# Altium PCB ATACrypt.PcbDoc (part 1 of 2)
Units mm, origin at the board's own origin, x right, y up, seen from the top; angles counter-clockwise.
Board outline 105.66 x 138.68 mm, 2 copper layers (Top Layer, Bottom Layer); 134 components, 213 nets, 662 pads, 171 vias.
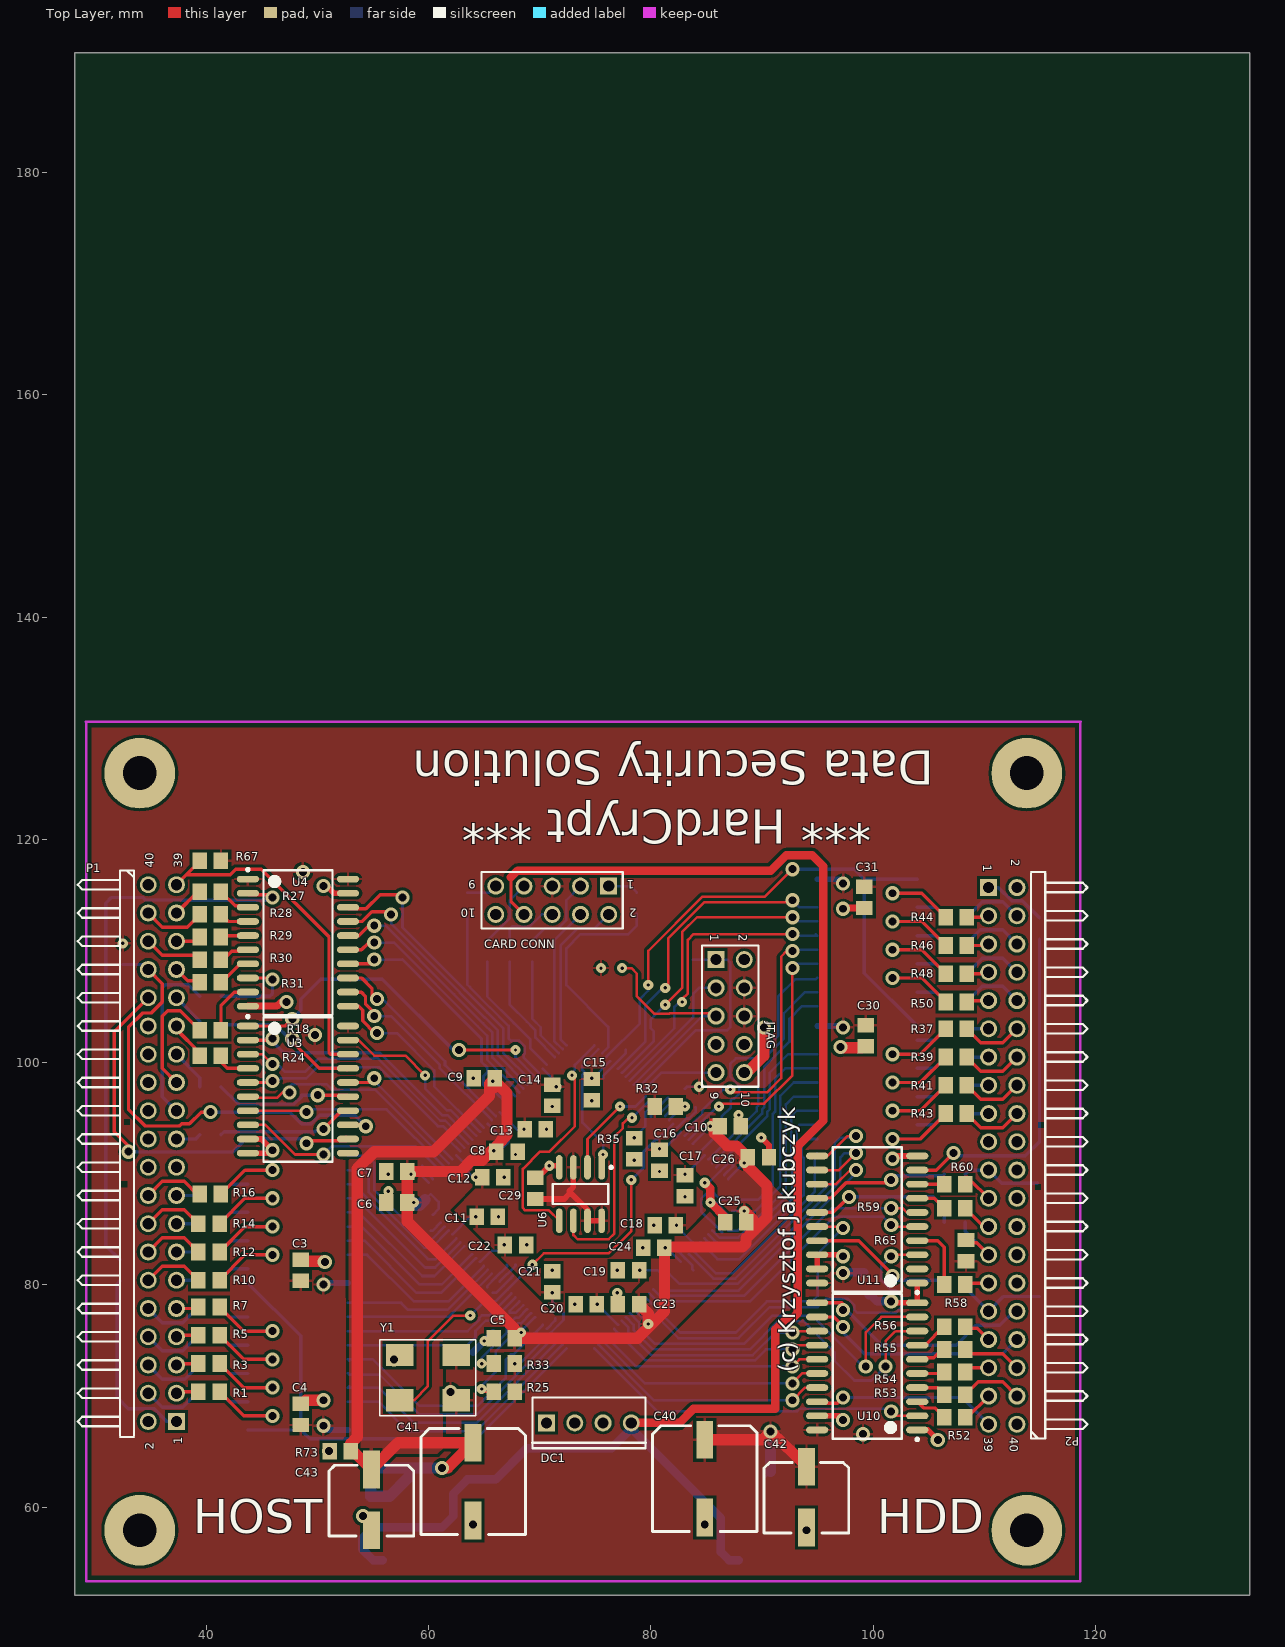
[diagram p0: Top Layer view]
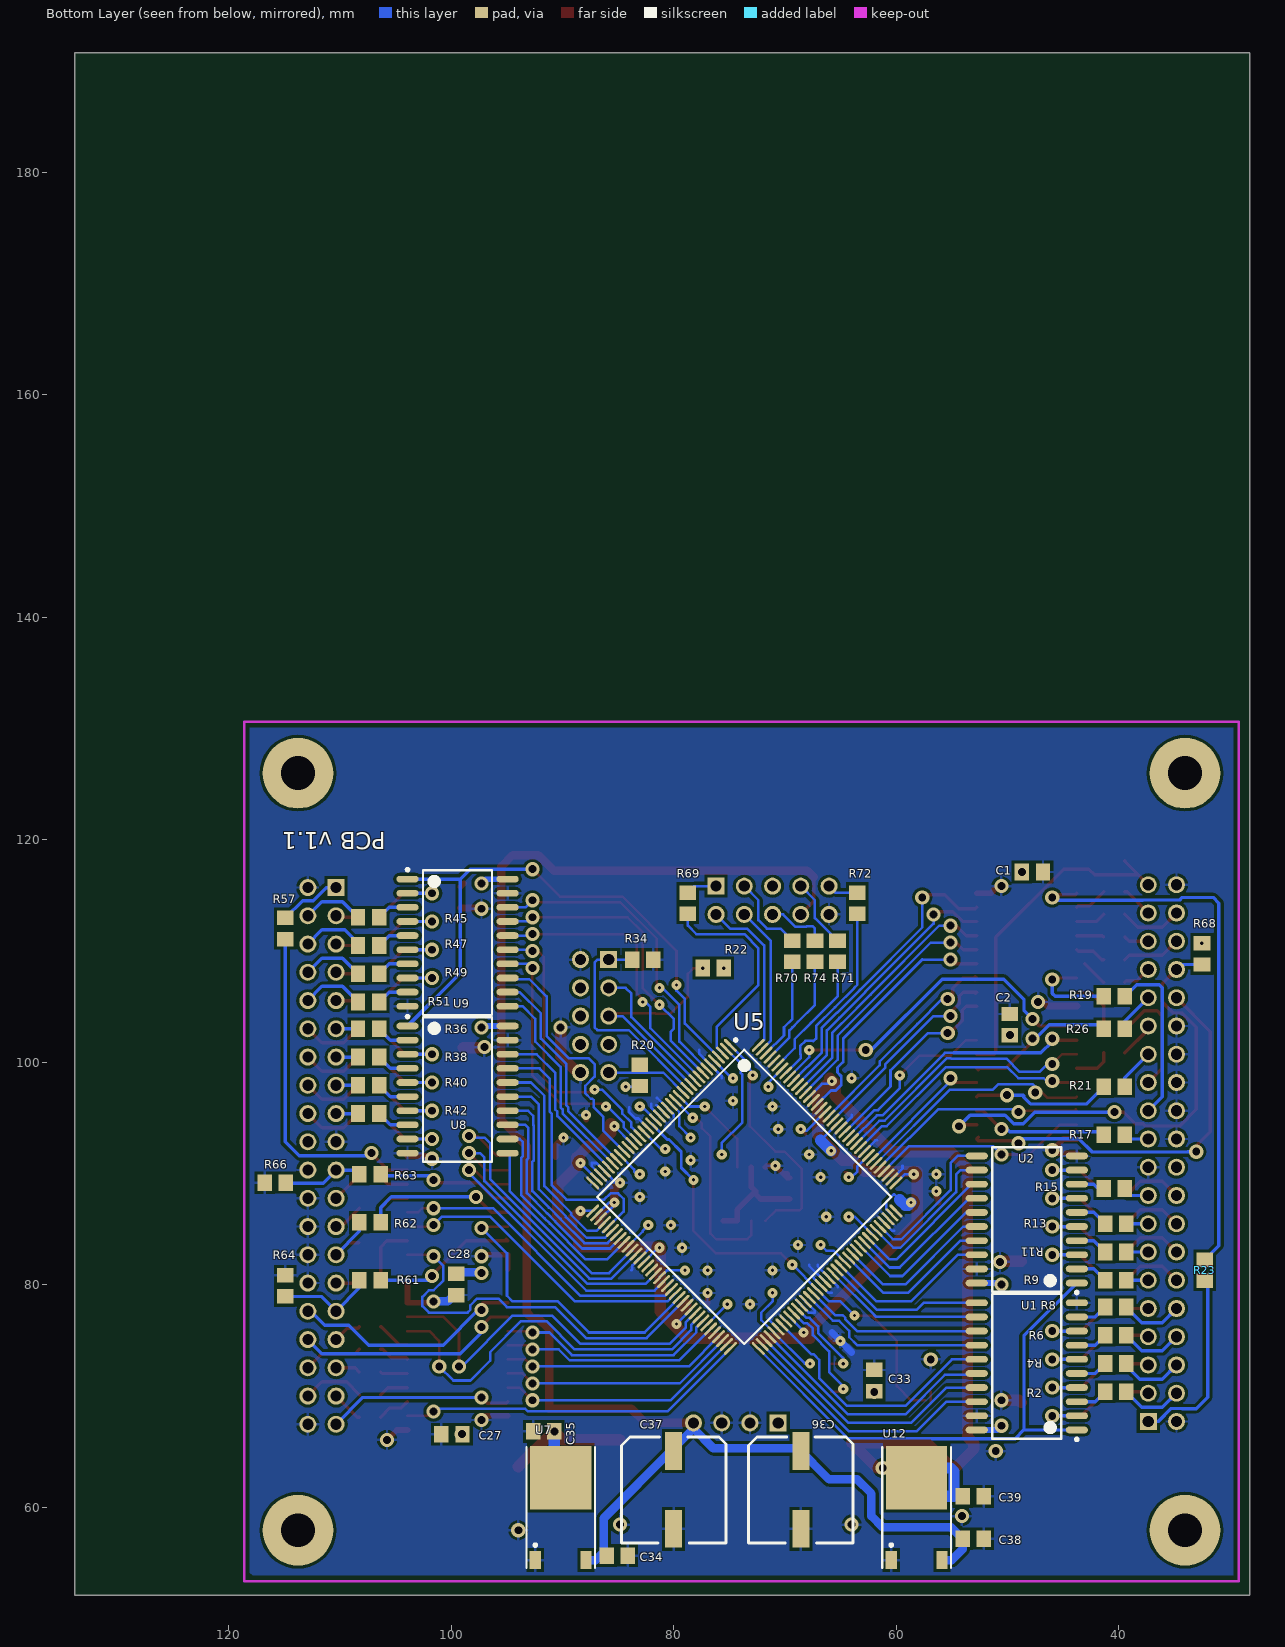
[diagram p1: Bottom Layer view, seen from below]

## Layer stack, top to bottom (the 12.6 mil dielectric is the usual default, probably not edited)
Top Layer: signal copper 0.0356
Dielectric: core 0.32, FR-4, Dk 4.8
Bottom Layer: signal copper 0.0356

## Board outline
28.194,52.07 133.858,52.07 133.858,190.754 28.194,190.754 28.194,52.07

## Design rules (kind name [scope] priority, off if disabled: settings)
Clearance [(InComponent('U5'))] p1: gap=0.178
Clearance Rest [All] p2: gap=0.254
ComponentClearance [All] p1: gap=0.254 collisioncheckmode=3 verticalgap=0.127 showdistances=FALSE
ComponentOrientations [All] p1: allowedrotations=32
HoleSize [All] p1: absolutevalues=TRUE maxlimit=3.048 minlimit=0.025 maxpercent=80.000 minpercent=20.000
MatchedLengths [InNetClass('HOST_DD_STROBE')] p1: tolerance=12.7 checknetsindiffpair=TRUE checkdiffpairvsdiffpair=TRUE checkothers=TRUE
MinimumSolderMaskSliver [All] p1: minsoldermaskwidth=0.201
PolygonConnect PolygonConnect_1 [All vs IsNamedPolygon('Top Layer-No Net')] p1: connectstyle=Relief reliefconductorwidth=0.254 reliefentries=4 polygonreliefangle="90 Angle"
PolygonConnect [All] p2: connectstyle=Relief reliefconductorwidth=0.254 reliefentries=4 polygonreliefangle="90 Angle"
RoomDefinition ATACrypt-Peripherial [InComponentClass('ATACrypt-Peripherial')] p1: confinementstyle=ConfineIn formatcopy=TRUE lockcomponents=FALSE outline 40.132,127 41.233,126.127 41.233,57.15 108.415,57.15 108.966,57.587 108.415,58.023 108.415,126.127
RoomDefinition ATACrypt-Device-Buf [InComponentClass('ATACrypt-Device-Buf')] p2: confinementstyle=ConfineIn formatcopy=TRUE lockcomponents=FALSE outline 78.232,123.444 78.467,123.19 119.888,123.19 119.888,59.436 118.711,58.166 118.476,58.42 78.467,58.42
RoomDefinition ATACrypt-Host-Buf [InComponentClass('ATACrypt-Host-Buf')] p3: confinementstyle=ConfineIn formatcopy=TRUE lockcomponents=FALSE outline 27.891,122.183 28.133,122.428 62.23,122.428 62.23,63.5 61.988,63.745 26.924,63.745
RoomDefinition ATACrypt-FPGA [InComponentClass('ATACrypt-FPGA')] p4: confinementstyle=ConfineIn formatcopy=TRUE lockcomponents=FALSE outline 54.61,62.738 95.758,62.738 95.758,113.538 54.61,113.538
RoomDefinition ATACrypt-Power [InComponentClass('ATACrypt-Power')] p5: confinementstyle=ConfineIn formatcopy=TRUE lockcomponents=FALSE outline 32.512,53.848 115.316,53.848 115.316,74.168 32.512,74.168
RoutingVias [All] p1: holewidth=0.305 width=0.914 viastyle="Through Hole" minholewidth=0.305 minwidth=0.914 maxholewidth=0.711 maxwidth=1.27
SMDNeckDown [All] p1: percent=110.000
SilkscreenOverComponentPads SD [(InComponent('MMC?'))] p1: minsilkscreentomaskgap=0
SilkscreenOverComponentPads 7805 [(InComponent('U7') OR InComponent('U12'))] p2: minsilkscreentomaskgap=0
SilkscreenOverComponentPads [All] p3: minsilkscreentomaskgap=0.254
SolderMaskExpansion [All] p1: expansion=0.127
TestPointUsage [All] p1: valid=0 allowmultiple=FALSE
Testpoint [All] p1: side=3 testpointundercomponent=TRUE minsize=1.016 maxsize=2.54 preferedsize=1.524 minholesize=0 maxholesize=1.016 preferedholesize=0.813 testpointgrid=0.025 style=297 order=0123456789
Width SUPPLY_GND [InNet('GND')] p1: maxlimit=1.016 minlimit=0.203 preferedwidth=1.016
Width SUPPLY_VCC [InNet('VCC33')OR InNet('VCC12')   OR InNet('VCC5')] p2: maxlimit=1.016 minlimit=0.203 preferedwidth=0.762
Width SIGNALS [All] p3: maxlimit=0.305 minlimit=0.203 preferedwidth=0.254
20 further rules are at their usual default settings.

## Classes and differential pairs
component class ATACrypt-Peripherial: C33 "CARD CONN" R69 R70 R71 R72 R74 Y1 Y?
polygon class PolygonClass_1: "Top Layer-No Net"
component class ATACrypt-Host-Buf: C1 C2 C3 C4 P1 R1 R2 R3 R4 R5 R6 R7 R8 R9 R10 R11 R12 R13 R14 R15 R16 R17 R18 R19 R21 R23 R24 R26 R27 R28 R29 R30 R31 R67 R68 U1 U2 U3 U4
component class ATACrypt-FPGA: C5 C6 C7 C8 C9 C10 C11 C12 C13 C14 C15 C16 C17 C18 C19 C20 C21 C22 C23 C24 C25 C26 C29 JTAG R20 R22 R25 R32 R33 R34 R35 U5 U6
component class ATACrypt-Device-Buf: C27 C28 C30 C31 P2 R36 R37 R38 R39 R40 R41 R42 R43 R44 R45 R46 R47 R48 R49 R50 R51 R52 R53 R54 R55 R56 R57 R58 R59 R60 R61 R62 R63 R64 R65 R66 U8 U9 U10 U11
component class ATACrypt-Power: C34 C35 C36 C37 C38 C39 C40 C41 C42 C43 DC1 R73 U7 U12

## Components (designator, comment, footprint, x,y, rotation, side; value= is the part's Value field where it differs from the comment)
C1 "Cap" 6-0805 47.752,117.094 r0 bottom
C2 "Cap" 6-0805 49.784,103.378 r270 bottom
C3 "Cap" 6-0805 48.514,81.28 r270 top
C4 "Cap" 6-0805 48.514,68.326 r270 top
C5 "Cap" 6-0805 66.802,75.184 r0 top
C6 "Cap" 6-0805 57.15,87.376 r0 top
C7 "Cap" 6-0805 57.15,90.17 r0 top
C8 "Cap" 6-0805 67.056,91.948 r180 top
C9 "Cap" 6-0805 65.024,98.552 r0 top
C10 "Cap" 6-0805 87.122,94.234 r180 top
C11 "Cap" 6-0805 65.278,86.106 r180 top
C12 "Cap" 6-0805 65.786,89.662 r180 top
C13 "Cap" 6-0805 69.596,93.98 r180 top
C14 "Cap" 6-0805 71.12,97.028 r90 top
C15 "Cap" 6-0805 74.676,97.536 r90 top
C16 "Cap" 6-0805 80.772,91.186 r90 top
C17 "Cap" 6-0805 83.058,88.9 r90 top
C18 "Cap" 6-0805 81.28,85.344 r0 top
C19 "Cap" 6-0805 77.978,81.28 r0 top
C20 "Cap" 6-0805 74.168,78.232 r0 top
C21 "Cap" 6-0805 71.12,80.264 r270 top
C22 "Cap" 6-0805 67.818,83.566 r180 top
C23 "Cap" 6-0805 77.978,78.232 r0 top
C24 "Cap" 6-0805 80.264,83.312 r0 top
C25 "Cap" 6-0805 87.63,85.598 r0 top
C26 "Cap" 6-0805 89.662,91.44 r180 top
C27 "Cap" 6-0805 99.949,66.548 r180 bottom
C28 "Cap" 6-0805 99.568,80.01 r90 bottom
C29 "Cap" 6-0805 69.596,88.646 r270 top
C30 "Cap" 6-0805 99.314,102.362 r90 top
C31 "Cap" 6-0805 99.187,114.808 r90 top
C33 "Cap" 6-0805 61.976,71.374 r270 bottom
C34 "Cap" 6-0805 85.09,55.626 r0 bottom
C35 "Cap" 6-0805 91.694,66.802 r180 bottom
C36 "Cap Pol1" "ELNA 100uF SMD" 68.58,61.722 r180 bottom
C37 "Cap Pol1" "ELNA 100uF SMD" 80.01,61.722 r180 bottom
C38 "Cap" 6-0805 53.086,57.15 r0 bottom
C39 "Cap" 6-0805 53.086,60.96 r0 bottom
C40 "Cap Pol1" "ELNA 100uF SMD" 84.836,62.738 r0 top
C41 "Cap Pol1" "ELNA 100uF SMD" 64.008,62.484 r0 top
C42 "Cap Pol1" "ELNA 47uF SMD" 93.98,59.69 r0 top
C43 "Cap Pol1" "ELNA 47uF SMD" 54.864,59.436 r0 top
"CARD CONN" "Header 5X2" HDR2X5#1 76.2,115.824 r180 top locked
DC1 "Molex-HDD" MOLEX-MINI-FDD 74.422,67.564 r180 top
JTAG "Header 5X2" HDR2X5#2 85.852,109.22 r270 top locked
P1 "HOST" LPH40 40.513,90.932 r270 top
P2 "HDD" LPH40 107.188,92.456 r90 top
R1 "Res2" 6-0805 40.259,70.358 r0 top
R2 "Res2" 6-0805 40.259,70.358 r0 bottom
R3 "Res2" 6-0805 40.259,72.898 r0 top
R4 "Res2" 6-0805 40.259,72.898 r0 bottom
R5 "Res2" 6-0805 40.259,75.438 r0 top
R6 "Res2" 6-0805 40.259,75.438 r0 bottom
R7 "Res2" 6-0805 40.259,77.978 r0 top
R8 "Res2" 6-0805 40.259,77.978 r0 bottom
R9 "Res2" 6-0805 40.259,80.391 r0 bottom
R10 "Res2" 6-0805 40.259,80.391 r0 top
R11 "Res2" 6-0805 40.259,82.931 r0 bottom
R12 "Res2" 6-0805 40.259,82.931 r0 top
R13 "Res2" 6-0805 40.259,85.471 r0 bottom
R14 "Res2" 6-0805 40.259,85.471 r0 top
R15 "Res2" 6-0805 40.386,88.646 r0 bottom
R16 "Res2" 6-0805 40.386,88.138 r0 top
R17 "Res2" 6-0805 40.386,93.472 r180 bottom
R18 "Res2" 6-0805 40.386,102.87 r0 top
R19 "Res2" 6-0805 40.386,105.918 r0 bottom
R20 "Res2" 6-0805 83.058,98.806 r270 bottom
R21 "Res2" 6-0805 40.386,97.79 r180 bottom
R22 "Res2" 6-0805 76.454,108.458 r180 bottom
R23 "Res2" 6-0805 32.258,81.28 r270 bottom
R24 "Res2" 6-0805 40.386,100.584 r0 top
R25 "Res2" 6-0805 66.802,70.358 r0 top
R26 "Res2" 6-0805 40.386,102.997 r180 bottom
R27 "Res2" 6-0805 40.386,115.316 r180 top
R28 "Res2" 6-0805 40.386,113.284 r180 top
R29 "Res2" 6-0805 40.386,111.252 r180 top
R30 "Res2" 6-0805 40.386,109.22 r180 top
R31 "Res2" 6-0805 40.386,107.188 r180 top
R32 "Res2" 6-0805 81.28,96.012 r180 top
R33 "Res2" 6-0805 66.802,72.898 r0 top
R34 "Res2" 6-0805 82.804,109.22 r0 bottom
R35 "Res2" 6-0805 78.486,92.202 r90 top
R36 "Res2" 6-0805 107.442,102.997 r180 bottom
R37 "Res2" 6-0805 107.442,102.997 r180 top
R38 "Res2" 6-0805 107.442,100.457 r180 bottom
R39 "Res2" 6-0805 107.442,100.457 r180 top
R40 "Res2" 6-0805 107.442,97.917 r180 bottom
R41 "Res2" 6-0805 107.442,97.917 r180 top
R42 "Res2" 6-0805 107.442,95.377 r180 bottom
R43 "Res2" 6-0805 107.442,95.377 r180 top
R44 "Res2" 6-0805 107.442,113.03 r180 top
R45 "Res2" 6-0805 107.442,113.03 r180 bottom
R46 "Res2" 6-0805 107.442,110.49 r180 top
R47 "Res2" 6-0805 107.442,110.49 r180 bottom
R48 "Res2" 6-0805 107.442,107.95 r180 top
R49 "Res2" 6-0805 107.442,107.95 r180 bottom
R50 "Res2" 6-0805 107.442,105.41 r180 top
R51 "Res2" 6-0805 107.442,105.41 r180 bottom
R52 "Res2" 6-0805 107.315,68.072 r0 top
R53 "Res2" 6-0805 107.315,70.104 r0 top
R54 "Res2" 6-0805 107.315,72.136 r0 top
R55 "Res2" 6-0805 107.315,74.168 r0 top
R56 "Res2" 6-0805 107.315,76.2 r0 top
R57 "Res2" 6-0805 114.935,112.014 r90 bottom
R58 "Res2" 6-0805 107.315,80.01 r180 top
R59 "Res2" 6-0805 107.315,86.868 r180 top
R60 "Res2" 6-0805 107.315,89.027 r180 top
R61 "Res2" 6-0805 107.315,80.391 r0 bottom
R62 "Res2" 6-0805 107.315,85.598 r0 bottom
R63 "Res2" 6-0805 107.315,89.916 r0 bottom
R64 "Res2" 6-0805 114.935,79.883 r270 bottom
R65 "Res2" 6-0805 108.331,83.058 r270 top
R66 "Res2" 6-0805 115.824,89.154 r180 bottom
R67 "Res2" 6-0805 40.386,118.11 r0 top
R68 "Res2" 6-0805 32.512,109.728 r90 bottom
R69 "Res2" 6-0805 78.74,114.3 r270 bottom
R70 "Res2" 6-0805 69.342,109.982 r270 bottom
R71 "Res2" 6-0805 65.278,109.982 r270 bottom
R72 "Res2" 6-0805 63.5,114.3 r270 bottom
R73 "Res2" 6-0805 52.07,65.024 r0 top
R74 "Res2" 6-0805 67.31,109.982 r90 bottom
U1 "SN74LVC245ADW" DW020_L 48.26,72.644 r0 bottom
U2 "SN74LVC245ADW" DW020_L 48.26,85.852 r0 bottom
U3 "SN74LVC245ADW" DW020_L 48.26,97.536 r0 top
U4 "SN74LVC245ADW" DW020_L 48.26,110.744 r0 top
U5 "EP2C8T144C8N" TQFP144_L 73.66,87.884 r225 bottom
U6 "EPCS4SI8N" SOIC8_N 73.66,88.138 r270 top
U7 "NCP1117DT33G" 369A-13 90.17,58.928 r180 bottom
U8 "SN74LVC245ADW" DW020_L 99.441,97.536 r180 bottom
U9 "SN74LVC245ADW" DW020_L 99.441,110.744 r180 bottom
U10 "SN74LVC245ADW" DW020_L 99.441,72.644 r180 top
U11 "SN74LVC245ADW" DW020_L 99.441,85.852 r180 top
U12 "LD1117DT12" 369A-13 58.166,58.928 r180 bottom
Y1 "CFPS-72-73" "Clock Oscillator SMD" 59.944,71.374 r180 top

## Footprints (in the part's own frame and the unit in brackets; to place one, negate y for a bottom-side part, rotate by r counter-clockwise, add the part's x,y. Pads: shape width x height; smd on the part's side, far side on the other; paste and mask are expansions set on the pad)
6-0805 [mm] "Chip Resistor; Body 2.0 x 1.3 mm (LxW typ)"
  rect 1.3x1.5 smd: 1(-0.95,0) 2(0.95,0)
369A-13 [mm] "D-PAK/TO-252-AA; 3 Leads (1 Cropped); Body 10.3 (inc. leads) x 6.7 mm (LxW max)"
  rect 1x1.6 smd: 1(-2.285,-3.7) 3(2.285,-3.7)
  rect 5.5x5.7 smd: 4(0,3.7)
  silkscreen extent -3.09,-4.4 3.09,6.45
"Clock Oscillator SMD" [mm] "Clock Oscillator SMD"
  rect 2.5x2 smd: 1(-2.54,-2.286) 2(2.54,-2.286) 3(2.54,1.778) 4(-2.54,1.778)
  silkscreen extent -4.32,-3.68 4.32,3.18
DW020_L [mm] "SOIC, 20-Leads, Body 12.8x7.5mm, Pitch 1.27mm, IPC High Density"
  oval 2x0.6 smd: 1(-4.5,5.715) 2(-4.5,4.445) 3(-4.5,3.175) 4(-4.5,1.905) 5(-4.5,0.635) 6(-4.5,-0.635) 7(-4.5,-1.905) 8(-4.5,-3.175) 9(-4.5,-4.445) 10(-4.5,-5.715) 11(4.5,-5.715) 12(4.5,-4.445) 13(4.5,-3.175) 14(4.5,-1.905) 15(4.5,-0.635) 16(4.5,0.635) 17(4.5,1.905) 18(4.5,3.175) 19(4.5,4.445) 20(4.5,5.715)
  silkscreen extent -4.62,-6.5 3.1,6.69, body extent -3.75,-6.4 3.75,6.4, height 2.65
"ELNA 47uF SMD" [mil] "ELNA 47uF SMD"
  rect 60x133.86 smd: 1(0,155) 2(0,-60)
  silkscreen extent -150,-80 150,170
"ELNA 100uF SMD" [mil] "ELNA 100uF SMD"
  rect 60x133.86 smd: 1(0,130) 2(0,-145)
  silkscreen extent -185,-195 185,180
HDR2X5#1 [mm] "Connector; Header; 5x2 Position"
  rect 1.525x1.525 hole 1.002 mask+0.127: 1(0,0)
  round 1.525 hole 1.002 mask+0.127: 2(0,2.54) 3(2.54,0) 4(2.54,2.54) 5(5.08,0) 6(5.08,2.54) 7(7.62,0) 8(7.62,2.54) 9(10.16,0) 10(10.16,2.54)
  silkscreen extent -1.27,-1.27 11.43,3.81
HDR2X5#2 [mm] "Connector; Header; 5x2 Position"
  rect 1.525x1.525 hole 1.002: 1(0,0)
  round 1.525 hole 1.002: 2(0,2.54) 3(2.54,0) 4(2.54,2.54) 5(5.08,0) 6(5.08,2.54) 7(7.62,0) 8(7.62,2.54) 9(10.16,0) 10(10.16,2.54)
  silkscreen extent -1.27,-1.27 11.43,3.81
LPH40 [mil] "Katowe 2x20"
  rect 60.05x60.05 hole 39.43: 1(915,-125)
  round 60.05 hole 39.43: 2(915,-225) 3(815,-125) 4(815,-225) 5(715,-125) 6(715,-225) 7(615,-125) 8(615,-225) 9(515,-125) 10(515,-225) 11(415,-125) 12(415,-225) 13(315,-125) 14(315,-225) 15(215,-125) 16(215,-225) 17(115,-125) 18(115,-225) 19(15,-125) 20(15,-225) 21(-85,-125) 22(-85,-225) 23(-185,-125) 24(-185,-225) 25(-285,-125) 26(-285,-225) 27(-385,-125) 28(-385,-225) 29(-485,-125) 30(-485,-225) 31(-585,-125) 32(-585,-225) 33(-685,-125) 34(-685,-225) 35(-785,-125) 36(-785,-225) 37(-885,-125) 38(-885,-225) 39(-985,-125) 40(-985,-225)
  silkscreen extent -1035,-475 970,-275
MOLEX-MINI-FDD [mm]
  rect 1.525x1.525 hole 1.002: 1(3.81,0)
  round 1.525 hole 1.002: 2(1.27,0) 3(-1.27,0) 4(-3.81,0)
  silkscreen extent -5.08,-2.29 5.08,2.29
SOIC8_N [mm] "SOIC, 8-Leads, Body 4.9x3.9mm, Pitch 1.27mm, IPC Medium Density"
  oval 2.2x0.6 smd: 1(-2.4,1.905) 2(-2.4,0.635) 3(-2.4,-0.635) 4(-2.4,-1.905) 5(2.4,-1.905) 6(2.4,-0.635) 7(2.4,0.635) 8(2.4,1.905)
  silkscreen extent -2.52,-2.5 0.9,2.88, body extent -1.95,-2.45 1.95,2.45, height 1.75
TQFP144_L [mm] "Thin QFP, 144-Leads, Body 20x20mm, Pitch 0.5mm, IPC High Density"
  oval 1.55x0.25 smd: 1(-10.525,8.75) 2(-10.525,8.25) 3(-10.525,7.75) 4(-10.525,7.25) 5(-10.525,6.75) 6(-10.525,6.25) 7(-10.525,5.75) 8(-10.525,5.25) 9(-10.525,4.75) 10(-10.525,4.25) 11(-10.525,3.75) 12(-10.525,3.25) 13(-10.525,2.75) 14(-10.525,2.25) 15(-10.525,1.75) 16(-10.525,1.25) 17(-10.525,0.75) 18(-10.525,0.25) 19(-10.525,-0.25) 20(-10.525,-0.75) 21(-10.525,-1.25) 22(-10.525,-1.75) 23(-10.525,-2.25) 24(-10.525,-2.75) 25(-10.525,-3.25) 26(-10.525,-3.75) 27(-10.525,-4.25) 28(-10.525,-4.75) 29(-10.525,-5.25) 30(-10.525,-5.75) 31(-10.525,-6.25) 32(-10.525,-6.75) 33(-10.525,-7.25) 34(-10.525,-7.75) 35(-10.525,-8.25) 36(-10.525,-8.75) 73(10.525,-8.75) 74(10.525,-8.25) 75(10.525,-7.75) 76(10.525,-7.25) 77(10.525,-6.75) 78(10.525,-6.25) 79(10.525,-5.75) 80(10.525,-5.25) 81(10.525,-4.75) 82(10.525,-4.25) 83(10.525,-3.75) 84(10.525,-3.25) 85(10.525,-2.75) 86(10.525,-2.25) 87(10.525,-1.75) 88(10.525,-1.25) 89(10.525,-0.75) 90(10.525,-0.25) 91(10.525,0.25) 92(10.525,0.75) 93(10.525,1.25) 94(10.525,1.75) 95(10.525,2.25) 96(10.525,2.75) 97(10.525,3.25) 98(10.525,3.75) 99(10.525,4.25) 100(10.525,4.75) 101(10.525,5.25) 102(10.525,5.75) 103(10.525,6.25) 104(10.525,6.75) 105(10.525,7.25) 106(10.525,7.75) 107(10.525,8.25) 108(10.525,8.75)
  oval 0.25x1.55 smd: 37(-8.75,-10.525) 38(-8.25,-10.525) 39(-7.75,-10.525) 40(-7.25,-10.525) 41(-6.75,-10.525) 42(-6.25,-10.525) 43(-5.75,-10.525) 44(-5.25,-10.525) 45(-4.75,-10.525) 46(-4.25,-10.525) 47(-3.75,-10.525) 48(-3.25,-10.525) 49(-2.75,-10.525) 50(-2.25,-10.525) 51(-1.75,-10.525) 52(-1.25,-10.525) 53(-0.75,-10.525) 54(-0.25,-10.525) 55(0.25,-10.525) 56(0.75,-10.525) 57(1.25,-10.525) 58(1.75,-10.525) 59(2.25,-10.525) 60(2.75,-10.525) 61(3.25,-10.525) 62(3.75,-10.525) 63(4.25,-10.525) 64(4.75,-10.525) 65(5.25,-10.525) 66(5.75,-10.525) 67(6.25,-10.525) 68(6.75,-10.525) 69(7.25,-10.525) 70(7.75,-10.525) 71(8.25,-10.525) 72(8.75,-10.525) 109(8.75,10.525) 110(8.25,10.525) 111(7.75,10.525) 112(7.25,10.525) 113(6.75,10.525) 114(6.25,10.525) 115(5.75,10.525) 116(5.25,10.525) 117(4.75,10.525) 118(4.25,10.525) 119(3.75,10.525) 120(3.25,10.525) 121(2.75,10.525) 122(2.25,10.525) 123(1.75,10.525) 124(1.25,10.525) 125(0.75,10.525) 126(0.25,10.525) 127(-0.25,10.525) 128(-0.75,10.525) 129(-1.25,10.525) 130(-1.75,10.525) 131(-2.25,10.525) 132(-2.75,10.525) 133(-3.25,10.525) 134(-3.75,10.525) 135(-4.25,10.525) 136(-4.75,10.525) 137(-5.25,10.525) 138(-5.75,10.525) 139(-6.25,10.525) 140(-6.75,10.525) 141(-7.25,10.525) 142(-7.75,10.525) 143(-8.25,10.525) 144(-8.75,10.525)
  silkscreen extent -10.65,-9.35 9.35,9.55, body extent -10,-10 10,10, height 1.6

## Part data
C1 C2 C3 C4 C5 C6 C7 C8 C9 C10 C11 C12 C13 C14 C15 C16 C17 C18 C19 C20 C21 C22 C23 C24 C25 C26 C27 C28 C29 C30 C31 C33 C34 C35 C38 C39: "Capacitor"
C36 C37 C40 C41 C42 C43: "Polarized Capacitor (Radial)"
"CARD CONN" JTAG: "Header, 5-Pin, Dual row"
DC1: "Zlacze dysku twardego Molex"
P1 P2: library part "Header 20X2H", "Header, 20-Pin, Dual row, Right Angle"
R1 R2 R3 R4 R5 R6 R7 R8 R9 R10 R11 R12 R13 R14 R15 R16 R17 R18 R19 R20 R21 R22 R23 R24 R25 R26 R27 R28 R29 R30 R31 R32 R33 R34 R35 R36 R37 R38 R39 R40 R41 R42 R43 R44 R45 R46 R47 R48 R49 R50 R51 R52 R53 R54 R55 R56 R57 R58 R59 R60 R61 R62 R63 R64 R65 R66 R67 R68 R69 R70 R71 R72 R73 R74: "Resistor"
U1 U2 U3 U4 U8 U9 U10 U11: "Octal Bus Transceiver with 3-State Outputs"
U5: "Cyclone II Family, 1.2V FPGA, 85 I/O Pins, 2 PLLs, 144-Pin TQFP, Speed Grade 8, Commercial Grade, Pb-Free"
U6: "EPCS4 Series, In-system programmable 3.3V serial configuration device, 8-Pin SOIC, 4-Megabit, Industrial Grade, Pb-Free"
U7 U12: library part MC33269T-3.3, "Low Dropout Positive Fixed Voltage Regulator"
Y1: "Clock oscillator SMD"

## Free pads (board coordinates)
  round 6.35 hole 3.048: 5(34.036,57.912) 5(34.036,125.984) 5(113.792,57.912) 5(113.792,125.984)

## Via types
v1: diameter 1.27, hole 0.711, Top Layer to Bottom Layer, 100 vias
v2: diameter 0.914, hole 0.305, Top Layer to Bottom Layer, 71 vias

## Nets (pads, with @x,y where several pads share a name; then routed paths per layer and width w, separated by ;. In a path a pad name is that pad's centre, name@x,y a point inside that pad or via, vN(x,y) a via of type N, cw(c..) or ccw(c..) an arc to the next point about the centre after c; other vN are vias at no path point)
ASDO: U5.1 U6.5 | length 21.7
  Top Layer w0.229: U6.5@71.755,85.738 70.815,86.678 68.693,86.678 68.478,86.893 68.478,90.399 70.027,91.948 70.866,91.948 73.152,94.234 73.152,98.552 v2(72.898,98.806) v2@72.898,99.06
  Bottom Layer w0.229: v2@72.898,99.06 73.152,99.314 73.152,99.75 U5.1@74.915,101.513
CLK: U5.21 U5.88 Y1.3 | length 41.8
  Top Layer w0.229: Y1.3@56.896,69.342 56.896,69.596 Y1.3@56.896,70.358 ; Y1.3@57.404,69.596 58.674,69.596 59.944,70.866 59.944,74.93 62.23,77.216 v2(63.754,77.216) ; v2(69.342,81.788) 70.358,82.804 76.2,82.804 78.232,84.836 v2(78.232,89.408)
  Bottom Layer w0.229: v2(63.754,77.216) 65.024,78.486 66.03,78.486 U5.88@67.102,79.558 67.112,79.558 v2(69.342,81.788)
  Bottom Layer w0.254: v2(78.232,89.408) 79.324,90.5 79.324,91.94 80.425,93.04 80.584,93.04 U5.21@81.986,94.442
CONF_DONE: R33.1 U5.83 | length 7.8
  Top Layer w0.229: v2(64.77,72.898) R33.1@65.852,72.898
  Bottom Layer w0.229: v2(64.77,72.898) 64.77,73.406 67.018,75.654 67.018,76.234 67.784,77 68.079,77 U5.83@68.869,77.79
D_CS0_N: P2.37 R52.2 | length 2.9
  Top Layer w0.305: R52.2@108.265,68.072 108.458,68.072 P2.37@110.363,69.977
D_CS1_N: P2.38 R53.2 | length 5.6
  Top Layer w0.305: R53.2@108.265,70.104 109.408,71.247 111.633,71.247 P2.38@112.903,69.977
D_DA0: P2.35 R54.2 | length 2.3
  Top Layer w0.305: R54.2@108.265,72.136 108.646,72.517 P2.35@110.363,72.517
D_DA1: P2.33 R56.2 | length 2.6
  Top Layer w0.305: R56.2@108.265,76.2 108.392,76.073 109.347,76.073 P2.33@110.363,75.057
D_DA2: P2.36 R55.2 | length 5.3
  Top Layer w0.305: R55.2@108.265,74.168 108.646,73.787 111.633,73.787 P2.36@112.903,72.517
D_DASP_N: P2.39 U10.18 | length 16.7
  Top Layer w0.305: U10.18@94.941,69.469 95.068,69.342 96.774,69.342 v1@97.028,69.596
  Bottom Layer w0.305: v1@97.028,69.596 v1(97.282,69.85) 107.95,69.85 P2.39@110.363,67.437
D_DD0: P2.17 R42.1 | length 2
  Bottom Layer w0.305: R42.1@108.392,95.377 P2.17@110.363,95.377
D_DD1: P2.15 R40.1 | length 2
  Bottom Layer w0.305: R40.1@108.392,97.917 P2.15@110.363,97.917
D_DD2: P2.13 R38.1 | length 2.2
  Top Layer w0.305: P2.13@110.236,100.33 P2.13@110.363,100.457
  Bottom Layer w0.305: R38.1@108.392,100.457 P2.13@110.363,100.457
D_DD3: P2.11 R36.1 | length 2
  Bottom Layer w0.305: R36.1@108.392,102.997 P2.11@110.363,102.997
D_DD4: P2.9 R50.1 | length 2
  Top Layer w0.305: R50.1@108.392,105.664 108.519,105.537 P2.9@110.363,105.537
D_DD5: P2.7 R48.1 | length 1.8
  Top Layer w0.305: R48.1@108.392,107.95 P2.7@110.236,107.95
D_DD6: P2.5 R46.1 | length 2.2
  Top Layer w0.305: R46.1@108.265,110.363 R46.1@108.392,110.49 P2.5@110.363,110.49
D_DD7: P2.3 R44.1 | length 2.3
  Top Layer w0.305: R44.1@108.265,113.411 108.519,113.157 108.646,113.03 P2.3@110.363,113.03
D_DD8: P2.4 R45.1 | length 5.6
  Bottom Layer w0.305: R45.1@108.392,113.03 109.789,114.427 111.633,114.427 P2.4@112.903,113.157
D_DD9: P2.6 R47.1 | length 5.9
  Bottom Layer w0.305: R47.1@108.265,110.363 108.265,110.49 108.265,110.551 108.298,110.584 109.601,111.887 111.633,111.887 P2.6@112.903,110.617
D_DD10: P2.8 R49.1 | length 5.6
  Bottom Layer w0.305: R49.1@108.392,107.95 109.789,109.347 111.633,109.347 P2.8@112.903,108.077
D_DD11: P2.10 R51.1 | length 5.6
  Bottom Layer w0.305: R51.1@108.392,105.41 109.789,106.807 111.633,106.807 P2.10@112.903,105.537
D_DD12: P2.12 R37.1 | length 5.6
  Top Layer w0.305: R37.1@108.392,102.997 109.662,101.727 111.633,101.727 P2.12@112.903,102.997
D_DD13: P2.14 R39.1 | length 5.6
  Top Layer w0.305: R39.1@108.392,100.457 109.662,99.187 111.633,99.187 P2.14@112.903,100.457
D_DD14: P2.16 R41.1 | length 5.6
  Top Layer w0.305: R41.1@108.392,97.917 109.662,96.647 111.633,96.647 P2.16@112.903,97.917
D_DD15: P2.18 R43.1 | length 5.6
  Top Layer w0.305: R43.1@108.392,95.377 109.662,94.107 111.633,94.107 P2.18@112.903,95.377
D_DIOR_N: P2.25 R59.1 | length 2.8
  Top Layer w0.305: R59.1@108.265,86.868 109.916,85.217 P2.25@110.363,85.217
D_DIOW_N: P2.23 R60.1 | length 2.9
  Top Layer w0.305: R60.1@108.265,89.662 108.458,89.662 108.679,89.441 P2.23@110.363,87.757
D_DMACK_N: P2.29 R58.1 | length 2.2
  Top Layer w0.305: R58.1@108.265,79.883 108.328,79.947 108.519,80.137 P2.29@110.363,80.137
D_DMARQ: P2.21 R63.2 R66.2 | length 7.3
  Top Layer w0.305: P2.21@110.236,90.424 P2.21@110.363,90.297
  Bottom Layer w0.305: R63.2@108.265,89.916 108.646,90.297 P2.21@110.363,90.297 111.532,89.128 114.721,89.128 R66.2@114.747,89.154
D_INTRQ: P2.31 R61.2 R64.2 | length 8.8
  Bottom Layer w0.305: R61.2@108.265,80.391 108.265,79.695 P2.31@110.363,77.597 111.699,78.933 R64.2@114.935,78.933
D_IOCS16: P2.32 U10.11 | length 21.1
  Top Layer w0.305: U10.11@94.941,78.359 97.155,78.359 97.282,78.232 v1(97.282,77.724)
  Bottom Layer w0.305: v1(97.282,77.724) 97.562,77.724 100.737,74.549 107.442,74.549 109.22,76.327 111.379,76.327 112.649,77.597 P2.32@112.903,77.597
D_IORDY: P2.27 R62.2 R65.1 | length 6.3
  Top Layer w0.305: R65.1@108.331,83.754 109.286,83.754 P2.27@110.363,82.677
  Bottom Layer w0.305: R62.2@108.265,85.598 108.265,84.775 P2.27@110.363,82.677
D_PDIAG_N: P2.34 U10.12 | length 20.2
  Top Layer w0.305: U10.12@94.941,77.089 96.444,77.089 97.028,76.505 v1@97.028,76.2
  Bottom Layer w0.305: v1@97.028,76.2 97.028,75.946 99.187,73.787 111.633,73.787 P2.34@112.903,75.057
  other v1: 97.282,76.2
D_RESET_N: P2.1 R57.2 | length 5.7
  Bottom Layer w0.305: P2.1@110.363,115.697 111.25,115.697 112.419,114.528 113.371,114.528 R57.2@114.935,112.964
DATA0: U5.14 U6.2 | length 9.4
  Top Layer w0.229: U6.2@74.295,90.538 74.295,93.091 v2(77.216,96.012)
  Bottom Layer w0.229: v2(77.216,96.012) 78.606,96.012 U5.14@79.511,96.917
DB_CS0_N: U5.71 U10.17 | length 22.2
  Top Layer w0.229: v1(92.71,69.596) 93.853,70.739 U10.17@94.941,70.739
  Bottom Layer w0.229: U5.71@75.269,74.608 80.281,69.596 v1(92.71,69.596)
DB_CS1_N: U5.70 U10.16 | length 21.3
  Top Layer w0.229: v1(92.71,71.12) 93.599,72.009 U10.16@94.941,72.009
  Bottom Layer w0.229: U5.70@75.622,74.962 79.464,71.12 v1(92.71,71.12)
DB_DA0: U5.69 U10.15 | length 20.3
  Top Layer w0.229: v1(92.71,72.644) 93.345,73.279 U10.15@94.941,73.279
  Bottom Layer w0.229: U5.69@75.976,75.315 78.647,72.644 v1(92.71,72.644)
DB_DA1: U5.65 U10.13 | length 20.3
  Top Layer w0.229: v1(92.71,75.692) 92.837,75.819 U10.13@94.941,75.819
  Bottom Layer w0.229: U5.65@77.39,76.729 77.965,76.154 77.965,75.712 80.018,73.66 89.154,73.66 91.186,75.692 v1(92.71,75.692) v1@92.456,75.438
DB_DA2: U5.67 U10.14 | length 20.2
  Top Layer w0.229: v1(92.71,74.168) 93.091,74.549 U10.14@94.941,74.549
  Bottom Layer w0.229: U5.67@76.683,76.022 78.973,73.732 ; 79.121,73.584 78.973,73.732 ; v1(92.71,74.168) 90.344,74.168 89.354,73.177 79.528,73.177 78.973,73.732
DB_DASP_N: U5.72 U10.2 | length 32.2
  Top Layer w0.229: v1@101.6,68.326 v1@101.727,68.199 ; v1(101.6,68.58) 101.981,68.199 U10.2@103.941,68.199
  Bottom Layer w0.229: U5.72@74.915,74.255 80.577,68.593 93.126,68.593 93.367,68.834 101.346,68.834 v1(101.6,68.58) ; v1@101.6,68.072 v1@101.6,68.326
DB_DD0: U5.45 U8.12 | length 19
  Bottom Layer w0.229: U5.45@84.461,83.8 85.965,82.296 87.971,82.296 91.148,85.472 91.148,85.48 91.613,85.946 91.621,85.946 93.726,88.051 93.726,91.391 93.573,91.544 93.573,92.811 93.853,93.091 U8.12@94.941,93.091 U8.12@94.566,93.091
DB_DD1: U5.43 U8.14 | length 19.1
  Bottom Layer w0.229: U5.43@85.168,84.508 85.949,83.726 88.037,83.726 90.183,85.872 90.183,85.896 91.198,86.911 91.221,86.911 92.71,88.4 92.71,91.042 92.608,91.144 92.608,94.306 92.634,94.332 92.634,95.174 93.091,95.631 U8.14@94.941,95.631
DB_DD2: U5.40 U8.16 | length 19.4
  Bottom Layer w0.229: U5.40@86.229,85.568 86.961,84.836 ; 87.043,84.836 87.781,84.836 89.218,86.272 89.218,86.423 91.642,88.848 91.642,94.706 ; 91.643,94.707 91.643,96.977 92.837,98.171 U8.16@94.941,98.171
  Bottom Layer w0.254: 86.961,84.836 87.043,84.836
DB_DD3: U5.32 U8.18 | length 15.4
  Bottom Layer w0.229: U5.32@85.875,90.553 90.475,95.153 90.475,95.553 90.678,95.756 90.678,99.06 92.329,100.711 U8.18@94.941,100.711
DB_DD4: U5.30 U9.12 | length 19.7
  Bottom Layer w0.229: U5.30@85.168,91.26 89.51,95.602 89.51,95.952 89.662,96.105 89.662,99.822 91.948,102.108 91.948,104.394 93.853,106.299 U9.12@94.941,106.299
DB_DD5: U5.25 U9.14 | length 24
  Top Layer w0.229: v2(86.106,96.012) 86.36,96.266 90.17,96.266 92.71,98.806 v1(92.71,108.458)
  Bottom Layer w0.229: U5.25@83.4,93.028 84.519,94.146 84.519,94.576 86.008,96.066 86.052,96.066 v2(86.106,96.012) ; v1(92.71,108.458) 93.091,108.839 U9.14@94.941,108.839
DB_DD6: U5.9 U9.16 | length 26.8
  Top Layer w0.229: v2(82.804,105.41) 82.804,105.664 83.312,106.172 83.312,110.998 83.82,111.506 v1(92.71,111.506)
  Bottom Layer w0.229: U5.9@77.744,98.685 82.105,103.047 82.105,104.966 82.55,105.41 v2(82.804,105.41) ; v1(92.71,111.506) 92.837,111.379 U9.16@94.941,111.379 U9.16@94.814,111.506
DB_DD7: U5.7 U9.18 | length 28.8
  Top Layer w0.229: v2(81.28,106.68) 81.534,106.934 81.534,111.104 84.821,114.391 92.547,114.391 v1(92.71,114.554)
  Bottom Layer w0.229: U5.7@77.036,99.392 79.502,101.858 79.502,105.156 81.026,106.68 v2(81.28,106.68) ; v1(92.71,114.554) 93.345,113.919 U9.18@94.941,113.919
DB_DD8: U5.8 U9.17 | length 28
  Top Layer w0.229: v2(81.28,105.156) 82.804,106.68 82.804,111.692 84.142,113.03 v1(92.71,113.03)
  Bottom Layer w0.229: U5.8@77.39,99.039 80.264,101.913 80.264,102.749 79.985,103.029 79.985,103.861 v2(81.28,105.156) ; v1(92.71,113.03) 93.091,112.649 U9.17@94.941,112.649
DB_DD9: U5.24 U9.15 | length 25.9
  Top Layer w0.229: v2(87.122,97.536) 87.376,97.282 90.424,97.282 91.694,98.552 91.694,109.474 92.202,109.982 v1(92.71,109.982)
  Bottom Layer w0.229: U5.24@83.047,93.382 83.82,94.155 83.82,94.56 84.62,95.36 84.62,95.694 86.463,97.536 v2(87.122,97.536) ; v1(92.71,109.982) 92.837,110.109 U9.15@94.941,110.109
DB_DD10: U5.28 U9.13 | length 22.8
  Bottom Layer w0.229: U5.28@84.461,91.968 86.36,93.867 86.36,95.099 87.185,95.924 87.185,96.584 87.312,96.71 87.464,96.71 87.947,97.194 87.947,97.878 87.122,98.703 87.122,99.822 87.63,100.33 89.408,100.33 91.44,102.362 91.44,105.918 92.977,107.455 94.827,107.455 U9.13@94.941,107.569
DB_DD11: U5.31 U9.11 | length 18.8
  Bottom Layer w0.229: U5.31@85.522,90.907 89.992,95.377 89.992,95.753 90.17,95.93 90.17,96.266 90.17,99.568 92.456,101.854 92.456,103.886 93.599,105.029 U9.11@94.941,105.029
DB_DD12: U5.41 U8.17 | length 25.1
  Bottom Layer w0.229: U5.41@86.398,84.692 U5.41@85.875,85.215 84.519,86.571 84.519,87.718 85.002,88.201 85.686,88.201 86.257,87.63 89.662,87.63 90.957,88.925 90.957,95.353 91.161,95.556 91.161,98.527 92.075,99.441 U8.17@94.941,99.441
DB_DD13: U5.42 U8.15 | length 19.5
  Bottom Layer w0.229: U5.42@85.522,84.861 86.174,84.209 87.837,84.209 89.7,86.072 89.7,86.144 92.125,88.569 92.125,94.506 ; 92.126,94.507 92.126,96.19 92.837,96.901 U8.15@94.941,96.901
DB_DD14: U5.44 U8.13 | length 18.7
  Bottom Layer w0.229: U5.44@84.815,84.154 85.725,83.244 88.237,83.244 90.665,85.672 90.665,85.696 91.398,86.428 91.421,86.428 93.218,88.225 93.218,91.216 93.09,91.344 93.09,94.106 93.345,94.361 U8.13@94.941,94.361
DB_DD15: U5.47 U8.11 | length 18.4
  Bottom Layer w0.229: U5.47@83.754,83.093 85.821,81.026 87.384,81.026 91.63,85.273 91.63,85.281 91.813,85.463 91.821,85.463 94.742,88.384 94.742,91.622 U8.11@94.941,91.821
DB_DD_DIR: U5.4 U8.1 U9.1 | length 53.9
  Top Layer w0.229: v2(79.756,106.934) 79.756,110.009 84.621,114.874 90.236,114.874 v1(92.71,117.348)
  Bottom Layer w0.229: U5.4@75.976,100.453 78.994,103.471 78.994,105.664 79.756,106.426 v2(79.756,106.934)
  Bottom Layer w0.305: v1(92.71,117.348) 98.298,117.348 99.187,116.459 ; U8.1@103.941,103.251 99.187,108.005 99.187,116.459 ; U9.1@103.941,116.459 99.187,116.459
DB_DIOR_N: U5.55 U11.13 | length 26.5
  Top Layer w0.229: U11.13@94.941,89.027 96.647,89.027 97.917,90.297 v1(98.425,90.297)
  Bottom Layer w0.229: U5.55@80.926,80.265 81.727,79.464 87.869,79.464 98.425,90.02 v1(98.425,90.297)
DB_DIOW_N: U5.53 U11.12 | length 27.4
  Top Layer w0.229: U11.12@94.941,90.297 96.901,90.297 v1(98.425,91.821)
  Bottom Layer w0.229: U5.53@81.633,80.972 82.55,80.055 87.778,80.055 97.028,89.305 97.028,91.44 97.409,91.821 v1(98.425,91.821)
DB_DMACK_N: U5.59 U11.16 | length 27.6
  Top Layer w0.229: U11.16@94.941,85.217 97.155,85.217 v1(97.282,85.09)
  Bottom Layer w0.229: U5.59@79.511,78.851 80.035,78.327 80.035,78.286 82.63,75.692 87.63,75.692 90.424,78.486 94.488,78.486 94.996,78.994 94.996,82.804 v1(97.282,85.09)
DB_DMARQ: U5.57 U11.6 | length 27.4
  Top Layer w0.229: v1(101.6,86.868) 102.616,86.868 102.997,86.487 U11.6@103.941,86.487
  Bottom Layer w0.229: U5.57@80.218,79.558 80.795,78.981 88.379,78.981 96.266,86.868 v1(101.6,86.868)
DB_INTRQ: U5.60 U11.3 | length 35.6
  Top Layer w0.229: v1(101.6,82.55) 101.727,82.677 U11.3@103.941,82.677
  Bottom Layer w0.229: U5.60@79.158,78.497 79.158,78.481 82.455,75.184 87.884,75.184 90.678,77.978 94.996,77.978 95.758,78.74 97.685,78.74 98.285,78.14 98.285,77.737 98.539,77.483 102.016,77.483 102.603,78.07 102.603,78.902 102.016,79.489 101.591,79.489 100.724,80.356 100.724,81.674 v1(101.6,82.55)
DB_IOCS16: U5.63 U10.9 | length 33.9
  Top Layer w0.229: v1(99.314,72.644) 99.314,75.692 100.711,77.089 U10.9@103.941,77.089
  Bottom Layer w0.229: U5.63@78.097,77.437 78.93,76.603 78.93,76.112 80.379,74.663 88.379,74.663 90.932,77.216 94.488,77.216 99.06,72.644 v1(99.314,72.644)
DB_IORDY: U5.58 U11.5 | length 28.1
  Top Layer w0.229: v1(101.6,85.344) 101.727,85.217 U11.5@103.941,85.217 U11.5@103.814,85.344
  Bottom Layer w0.229: U5.58@79.865,79.204 80.583,78.486 88.9,78.486 96.52,86.106 100.838,86.106 v1(101.6,85.344)
DB_PDIAG_N: U5.64 U10.8 | length 34.6
  Top Layer w0.229: v1(101.092,72.644) 101.092,74.93 101.981,75.819 U10.8@103.941,75.819
  Bottom Layer w0.229: U5.64@77.744,77.083 78.448,76.379 78.448,75.912 80.179,74.181 88.913,74.181 91.44,76.708 93.726,76.708 96.52,73.914 96.52,73.152 98.298,71.374 99.822,71.374 v1(101.092,72.644)
DB_RESET_N: U5.48 U11.11 | length 27.4
  Top Layer w0.229: U11.11@94.941,91.567 95.885,91.567 97.663,93.345 v1(98.425,93.345)
  Bottom Layer w0.229: U5.48@83.4,82.74 85.603,80.537 87.578,80.537 96.52,89.48 96.52,92.71 97.028,93.218 98.298,93.218 v1(98.425,93.345)
DCLK: U5.15 U6.6 | length 18.9
  Top Layer w0.229: U6.6@73.025,85.738 73.025,84.455 73.406,84.074 76.2,84.074 76.708,84.582 76.708,93.295 77.47,94.057 77.47,94.488 77.978,94.996 v2(78.297,94.996)
  Bottom Layer w0.229: v2@78.232,94.996 v2(78.297,94.996) U5.15@79.865,96.564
